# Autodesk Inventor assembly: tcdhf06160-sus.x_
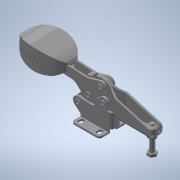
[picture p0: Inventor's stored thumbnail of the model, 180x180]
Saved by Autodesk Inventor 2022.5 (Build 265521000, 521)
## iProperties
Part Number: tcdhf06160-sus.x_
Material: 一般
Document SubType Name: Assembly
Designer: ImaoCorp
Sending System: SOLIDWORKS 2017-2017317
MC: AMD64
MC_MODEL: Intel64 Family 6 Model 60 Stepping 3, GenuineIntel
OS: Windows_NT
FRU: Parasolid Version 29.0, build 201,  4-17-2017
FORMAT: text
GUISE: transmit
KEY: tcdhf06160-sus
FILE: tcdhf06160-sus.x_t
DATE: Wed Sep 18 16:30:54 2019
Author: ImaoCorp
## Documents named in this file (8)
- X:\14_SW2022-Inv2022\00_全2023-1023新製品(TCC)まで\t\tcdhf06160-sus\TCDHF06160-SUS.iam
- X:\14_SW2022-Inv2022\00_全2023-1023新製品(TCC)まで\t\tcdhf06160-sus\tcdhf06160-sus_01.ipt
- X:\14_SW2022-Inv2022\00_全2023-1023新製品(TCC)まで\t\tcdhf06160-sus\tcdhf06160-sus_02.ipt
- X:\14_SW2022-Inv2022\00_全2023-1023新製品(TCC)まで\t\tcdhf06160-sus\tcdhf06160-sus_03.ipt
- X:\14_SW2022-Inv2022\00_全2023-1023新製品(TCC)まで\t\tcdhf06160-sus\tcdhf06160-sus_04.ipt
- X:\14_SW2022-Inv2022\00_全2023-1023新製品(TCC)まで\t\tcdhf06160-sus\tcdhf06160-sus_05.ipt
- X:\14_SW2022-Inv2022\00_全2023-1023新製品(TCC)まで\t\tcdhf06160-sus\tcdhf06160-sus_06.ipt
- X:\14_SW2022-Inv2022\00_全2023-1023新製品(TCC)まで\t\tcdhf06160-sus\tcdhf06160-sus_07.ipt
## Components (7 placed, 7 different names)
1. tcdhf06160-sus_01
2. tcdhf06160-sus_02
3. tcdhf06160-sus_03
4. tcdhf06160-sus_04
5. tcdhf06160-sus_05
6. tcdhf06160-sus_06
7. tcdhf06160-sus_07
